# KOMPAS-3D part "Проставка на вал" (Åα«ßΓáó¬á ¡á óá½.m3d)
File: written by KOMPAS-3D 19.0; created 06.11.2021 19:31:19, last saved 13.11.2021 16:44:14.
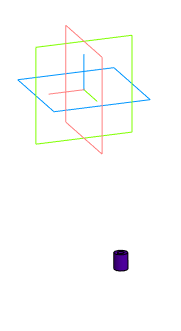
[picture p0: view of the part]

Document properties: Полное имя файла: D:\3D_print\3D проекты Компас 3D\Редуктор (Снова)\Проставка на вал.m3d

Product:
- Part/product: Проставка на вал
    Материал: АБС 0603Т ТУ 2214-019-002 03521-96 (density 0 kg/m3)

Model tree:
1. Эскиз:1
2. Элемент выдавливания:1  (labels: Reductor\Korpus(2); АБС 0603Т ТУ 2214-019-002 03521-96)
     Расстояние 1 = 8.3; Смещение 1 = 1

Referenced files in D:\3D_print\3D проекты Компас 3D\Редуктор (Снова)\: Намоточный станок (Projects 6).a3d
Referenced files in C:\Program Files\ASCON\KOMPAS-3D v19\Libs\PARTLib\DATA\vault\Methods\Kompas\3D\: PLib_Nut_OST92_900.m3d
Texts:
  Намоточный станок (Projects 5)\Reductor\Гайка М3-6H ГОСТ 5915-70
